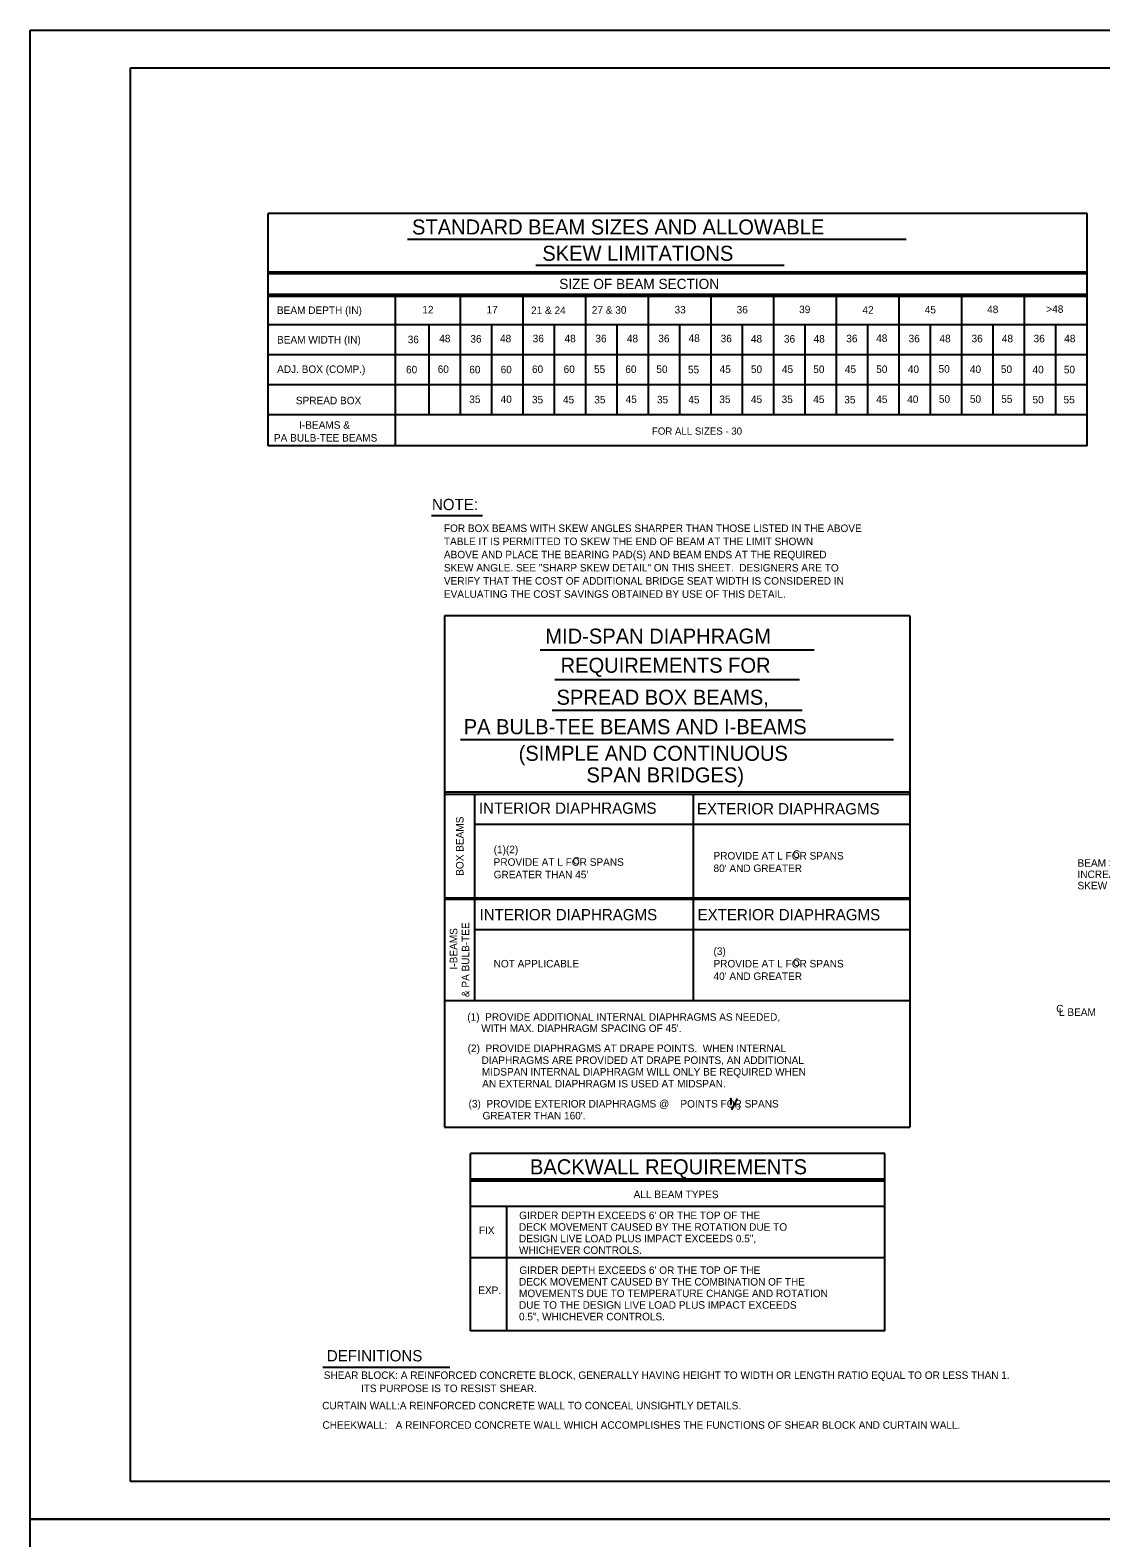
# Model space of a CAD drawing. Extents: x 638791 to 639830, y 298565 to 299753.
# Drawn here: x 638974 to 639402, y 299152 to 299753 of the extents above; entities that cross this region are included whole.
import ezdxf

# ---------------------------------------------------------------- set-up
doc = ezdxf.new("R2010")
doc.units = 0
doc.layers.add('2', color=7, linetype='Continuous')
doc.layers.add('PLT-BNDY', color=7, linetype='Continuous')

msp = doc.modelspace()

# ---------------------------------------------------------------- linework, layer by layer
at = {"layer": '2'}
for p, q in [((639014.29, 299174.48), (639014.29, 299738.48)), ((639014.29, 299738.48), (639800.29, 299738.48)), ((639396.04, 299680.33), (639069.29, 299680.33)), ((639069.29, 299587.58), (639069.29, 299680.33)), ((639396.04, 299587.58), (639396.04, 299680.33)), ((639124.92, 299670.08), (639323.92, 299670.08)), ((639396.04, 299656.96), (639069.29, 299656.96)), ((639396.04, 299656.21), (639069.29, 299656.21)), ((639176.04, 299659.71), (639275.17, 299659.71)), ((639396.04, 299647.96), (639069.29, 299647.96)), ((639396.04, 299647.21), (639069.29, 299647.21)), ((639120.04, 299587.58), (639120.04, 299647.21)), ((639146.04, 299599.96), (639146.04, 299647.21)), ((639171.04, 299599.96), (639171.04, 299647.21)), ((639196.04, 299599.96), (639196.04, 299647.21)), ((639221.04, 299599.96), (639221.04, 299647.21)), ((639246.04, 299599.96), (639246.04, 299647.21)), ((639271.04, 299599.96), (639271.04, 299647.21)), ((639296.04, 299599.96), (639296.04, 299647.21)), ((639321.04, 299599.96), (639321.04, 299647.21)), ((639346.04, 299599.96), (639346.04, 299647.21)), ((639371.04, 299599.96), (639371.04, 299647.21)), ((639396.04, 299635.96), (639069.29, 299635.96)), ((639133.54, 299599.96), (639133.54, 299635.96)), ((639158.54, 299599.96), (639158.54, 299635.96)), ((639183.54, 299599.96), (639183.54, 299635.96)), ((639208.54, 299599.96), (639208.54, 299635.96)), ((639233.54, 299599.96), (639233.54, 299635.96)), ((639258.54, 299599.96), (639258.54, 299635.96)), ((639283.54, 299599.96), (639283.54, 299635.96)), ((639283.54, 299599.96), (639283.54, 299635.96)), ((639308.54, 299599.96), (639308.54, 299635.96)), ((639333.54, 299599.96), (639333.54, 299635.96)), ((639358.54, 299599.96), (639358.54, 299635.96)), ((639383.54, 299599.96), (639383.54, 299635.96)), ((639396.04, 299623.96), (639069.29, 299623.96)), ((639396.04, 299611.96), (639069.29, 299611.96)), ((639396.04, 299599.96), (639069.29, 299599.96)), ((639396.04, 299587.58), (639069.29, 299587.58)), ((639154.76, 299559.75), (639134.51, 299559.75)), ((639139.61, 299519.85), (639139.61, 299315.85)), ((639325.36, 299519.85), (639139.61, 299519.85)), ((639325.36, 299519.85), (639325.36, 299315.85)), ((639177.82, 299506.23), (639287.14, 299506.23)), ((639183.66, 299494.48), (639281.3, 299494.48)), ((639182.54, 299482.23), (639282.42, 299482.23)), ((639139.61, 299472.6), (639139.61, 299400.6)), ((639145.98, 299470.48), (639318.82, 299470.48)), ((639325.36, 299449.48), (639139.61, 299449.48)), ((639325.36, 299448.6), (639139.61, 299448.6)), ((639151.61, 299448.6), (639151.61, 299366.17)), ((639238.86, 299448.6), (639238.86, 299366.17)), ((639325.36, 299436.6), (639151.61, 299436.6)), ((639325.36, 299407.23), (639139.61, 299407.23)), ((639325.36, 299406.6), (639139.61, 299406.6)), ((639325.36, 299394.6), (639151.61, 299394.6)), ((639325.36, 299366.17), (639139.61, 299366.17)), ((639139.61, 299315.85), (639325.36, 299315.85)), ((639315.36, 299305.26), (639149.99, 299305.26)), ((639149.99, 299234.51), (639149.99, 299305.26)), ((639315.36, 299234.51), (639315.36, 299305.26)), ((639315.36, 299295.14), (639149.99, 299295.14)), ((639315.36, 299294.26), (639149.99, 299294.26)), ((639315.11, 299284.14), (639149.86, 299284.14)), ((639164.49, 299234.89), (639164.49, 299284.14)), ((639315.24, 299263.76), (639149.86, 299263.76)), ((639315.36, 299234.51), (639149.99, 299234.51)), ((639091.07, 299220.13), (639141.82, 299220.13)), ((639800.29, 299174.48), (639014.29, 299174.48))]:
    msp.add_line(p, q, dxfattribs=at)
for points in [[(639253.7, 299327.1), (639253.88, 299327.31), (639253.88, 299325.06), (639253.7, 299325.06), (639254.06, 299325.06)], [(639254.28, 299322.79), (639256.52, 299327.3)]]:
    msp.add_lwpolyline(points, dxfattribs=at)
at = {"layer": 'PLT-BNDY'}
for points in [[(638974.29, 299753.48), (639815.29, 299753.48), (639815.29, 299159.48), (638974.29, 299159.48)], [(638974.29, 299159.48), (639815.29, 299159.48), (639815.29, 298565.48), (638974.29, 298565.48)]]:
    msp.add_lwpolyline(points, close=True, dxfattribs=at)

# ---------------------------------------------------------------- texts
at = {"layer": '2'}
for s, height, p in [('STANDARD BEAM SIZES AND ALLOWABLE', 6, (639126.67, 299671.96)), ('SKEW LIMITATIONS', 6, (639178.67, 299661.46)), ('SIZE OF BEAM SECTION', 4.0695, (639185.42, 299650.21)), ('BEAM DEPTH (IN)', 3, (639072.78, 299640.25)), ('12', 3, (639130.8, 299640.47)), ('17', 3, (639156.43, 299640.47)), ('21 & 24', 3, (639174.18, 299640.22)), ('27 & 30', 3, (639198.43, 299640.34)), ('33', 3, (639231.43, 299640.47)), ('36', 3, (639256.22, 299640.47)), ('39', 3, (639281.17, 299640.59)), ('42', 3, (639306.41, 299640.34)), ('45', 3, (639331.29, 299640.47)), ('48', 3, (639356.17, 299640.59)), ('>48', 3, (639379.79, 299640.72)), ('BEAM WIDTH (IN)', 3, (639072.81, 299628.46)), ('36', 3, (639124.96, 299628.58)), ('48', 3, (639137.54, 299628.96)), ('36', 3, (639149.96, 299628.83)), ('48', 3, (639161.79, 299628.96)), ('36', 3, (639174.84, 299628.96)), ('48', 3, (639187.54, 299628.96)), ('36', 3, (639199.84, 299628.96)), ('48', 3, (639212.41, 299628.96)), ('36', 3, (639224.96, 299628.96)), ('48', 3, (639237.04, 299629.08)), ('36', 3, (639249.84, 299628.96)), ('48', 3, (639261.91, 299628.83)), ('36', 3, (639275.09, 299628.83)), ('48', 3, (639286.91, 299628.83)), ('36', 3, (639299.96, 299628.96)), ('48', 3, (639311.91, 299629.08)), ('36', 3, (639324.84, 299628.96)), ('48', 3, (639337.16, 299628.96)), ('36', 3, (639349.96, 299628.96)), ('48', 3, (639362.04, 299628.96)), ('36', 3, (639374.71, 299628.96)), ('48', 3, (639386.95, 299628.96)), ('ADJ. BOX (COMP.)', 3, (639072.84, 299616.71)), ('60', 3, (639124.29, 299616.58)), ('60', 3, (639136.92, 299616.71)), ('60', 3, (639149.54, 299616.58)), ('60', 3, (639162.04, 299616.58)), ('60', 3, (639174.54, 299616.71)), ('60', 3, (639187.17, 299616.71)), ('55', 3, (639199.29, 299616.71)), ('60', 3, (639211.79, 299616.71)), ('50', 3, (639224.17, 299616.71)), ('55', 3, (639236.79, 299616.58)), ('45', 3, (639249.42, 299616.71)), ('50', 3, (639261.92, 299616.71)), ('45', 3, (639274.29, 299616.71)), ('50', 3, (639286.79, 299616.71)), ('45', 3, (639299.42, 299616.71)), ('50', 3, (639311.92, 299616.71)), ('40', 3, (639324.54, 299616.71)), ('50', 3, (639336.79, 299616.83)), ('40', 3, (639349.29, 299616.71)), ('50', 3, (639361.67, 299616.71)), ('40', 3, (639374.29, 299616.58)), ('50', 3, (639386.79, 299616.58)), ('SPREAD BOX', 3, (639080.33, 299604.21)), ('35', 3, (639149.54, 299604.71)), ('40', 3, (639162.04, 299604.71)), ('35', 3, (639174.54, 299604.58)), ('45', 3, (639186.92, 299604.58)), ('35', 3, (639199.42, 299604.58)), ('45', 3, (639211.92, 299604.71)), ('35', 3, (639224.42, 299604.58)), ('45', 3, (639236.92, 299604.58)), ('35', 3, (639249.29, 299604.71)), ('45', 3, (639261.92, 299604.71)), ('35', 3, (639274.17, 299604.71)), ('45', 3, (639286.79, 299604.71)), ('35', 3, (639299.17, 299604.58)), ('45', 3, (639311.92, 299604.71)), ('40', 3, (639324.29, 299604.71)), ('50', 3, (639336.92, 299604.83)), ('50', 3, (639349.29, 299604.83)), ('55', 3, (639361.79, 299604.83)), ('50', 3, (639374.29, 299604.58)), ('55', 3, (639386.67, 299604.58)), ('I-BEAMS &', 3, (639081.63, 299594.46)), ('PA BULB-TEE BEAMS', 3, (639071.58, 299589.33)), ('FOR ALL SIZES - 30', 2.88, (639222.42, 299592.08)), ('NOTE:', 4.5, (639134.63, 299562)), ('FOR BOX BEAMS WITH SKEW ANGLES SHARPER THAN THOSE LISTED IN THE ABOVE', 3, (639139.4, 299553.27)), ('TABLE IT IS PERMITTED TO SKEW THE END OF BEAM AT THE LIMIT SHOWN', 3, (639139.4, 299548.02)), ('ABOVE AND PLACE THE BEARING PAD(S) AND BEAM ENDS AT THE REQUIRED', 3, (639139.4, 299542.77)), ('VERIFY THAT THE COST OF ADDITIONAL BRIDGE SEAT WIDTH IS CONSIDERED IN', 3, (639139.4, 299532.27)), ('SKEW ANGLE. SEE "SHARP SKEW DETAIL" ON THIS SHEET.  DESIGNERS ARE TO', 3, (639139.4, 299537.52)), ('EVALUATING THE COST SAVINGS OBTAINED BY USE OF THIS DETAIL.', 3, (639139.4, 299527.02)), ('MID-SPAN DIAPHRAGM', 6, (639179.87, 299508.73)), ('REQUIREMENTS FOR', 6, (639185.97, 299497.1)), ('SPREAD BOX BEAMS,', 6, (639184.35, 299484.35)), ('PA BULB-TEE BEAMS AND I-BEAMS', 6, (639147.3, 299472.6)), ('(SIMPLE AND CONTINUOUS', 6, (639169.23, 299461.98)), ('SPAN BRIDGES)', 6, (639196.29, 299453.35)), ('INTERIOR DIAPHRAGMS', 4.5, (639153.36, 299440.85)), ('EXTERIOR DIAPHRAGMS', 4.5, (639240.36, 299440.6)), ('(1)(2)', 3, (639159.25, 299425.1)), ('PROVIDE AT L FOR SPANS', 3, (639159.25, 299420.1)), ('C', 2.88, (639190.85, 299420.69)), ('PROVIDE AT L FOR SPANS', 3, (639246.99, 299422.6)), ('C', 3, (639278.68, 299423.26)), ('BEAM SEAT WIDTH MUST BE', 3, (639392.25, 299419.71)), ("GREATER THAN 45'", 3, (639159.25, 299415.1)), ("80' AND GREATER", 3, (639246.99, 299417.6)), ('INCREASED TO ACCOMMODATE', 3, (639392.25, 299415.21)), ('SKEW OF P/S BEAM END', 3, (639392.25, 299410.71)), ('INTERIOR DIAPHRAGMS', 4.5, (639153.61, 299398.35)), ('EXTERIOR DIAPHRAGMS', 4.5, (639240.61, 299398.35)), ('(3)', 3, (639246.99, 299384.55)), ('NOT APPLICABLE', 3, (639159.25, 299379.55)), ('PROVIDE AT L FOR SPANS', 3, (639246.99, 299379.55)), ('C', 3, (639278.76, 299380.12)), ("40' AND GREATER", 3, (639246.99, 299374.55)), ('(1)  PROVIDE ADDITIONAL INTERNAL DIAPHRAGMS AS NEEDED,', 3, (639148.73, 299358.29)), ('C', 3, (639383.76, 299361.6)), ('L BEAM', 3, (639384.85, 299360.23)), ("     WITH MAX. DIAPHRAGM SPACING OF 45'.", 3, (639148.73, 299353.79)), ('(2)  PROVIDE DIAPHRAGMS AT DRAPE POINTS.  WHEN INTERNAL', 3, (639148.86, 299345.79)), ('     DIAPHRAGMS ARE PROVIDED AT DRAPE POINTS, AN ADDITIONAL', 3, (639148.86, 299341.04)), ('     MIDSPAN INTERNAL DIAPHRAGM WILL ONLY BE REQUIRED WHEN', 3, (639148.98, 299336.42)), ('     AN EXTERNAL DIAPHRAGM IS USED AT MIDSPAN.', 3, (639149.11, 299331.67)), ('(3)  PROVIDE EXTERIOR DIAPHRAGMS @    POINTS FOR SPANS', 3, (639149.23, 299323.67)), ('3', 2.25, (639256.03, 299322.79)), ("     GREATER THAN 160'.", 3, (639149.23, 299318.92)), ('BACKWALL REQUIREMENTS', 6, (639173.74, 299297.01)), ('ALL BEAM TYPES', 3, (639215.11, 299287.51)), ("GIRDER DEPTH EXCEEDS 6' OR THE TOP OF THE", 3, (639169.45, 299279.14)), ('DECK MOVEMENT CAUSED BY THE ROTATION DUE TO', 3, (639169.37, 299274.51)), ('FIX', 3, (639153.36, 299273.14)), ('DESIGN LIVE LOAD PLUS IMPACT EXCEEDS 0.5",', 3, (639169.37, 299269.89)), ('WHICHEVER CONTROLS.', 3, (639169.37, 299265.26)), ("GIRDER DEPTH EXCEEDS 6' OR THE TOP OF THE", 3, (639169.49, 299257.26)), ('DECK MOVEMENT CAUSED BY THE COMBINATION OF THE', 3, (639169.37, 299252.64)), ('EXP.', 3, (639153.11, 299249.26)), ('MOVEMENTS DUE TO TEMPERATURE CHANGE AND ROTATION', 3, (639169.37, 299248.01)), ('DUE TO THE DESIGN LIVE LOAD PLUS IMPACT EXCEEDS ', 3, (639169.37, 299243.39)), ('0.5", WHICHEVER CONTROLS.', 3, (639169.37, 299238.76)), ('DEFINITIONS', 4.5, (639092.69, 299222.38)), ('SHEAR BLOCK: A REINFORCED CONCRETE BLOCK, GENERALLY HAVING HEIGHT TO WIDTH OR LENGTH RATIO EQUAL TO OR LESS THAN 1.', 3, (639091.44, 299215.38)), ('             ITS PURPOSE IS TO RESIST SHEAR.', 3, (639091.82, 299210.13)), ('CURTAIN WALL:A REINFORCED CONCRETE WALL TO CONCEAL UNSIGHTLY DETAILS.', 3, (639090.82, 299203.25)), ('CHEEKWALL:   A REINFORCED CONCRETE WALL WHICH ACCOMPLISHES THE FUNCTIONS OF SHEAR BLOCK AND CURTAIN WALL.', 3, (639090.94, 299195.5))]:
    msp.add_text(s, height=height, dxfattribs=at).set_placement(p)
for s, p in [('BOX BEAMS', (639147.23, 299416.1)), ('& PA BULB-TEE', (639149.53, 299367.7)), ('I-BEAMS', (639144.76, 299378.75))]:
    msp.add_text(s, height=3, rotation=90, dxfattribs=at).set_placement(p)

doc.saveas('drawing.dxf')
